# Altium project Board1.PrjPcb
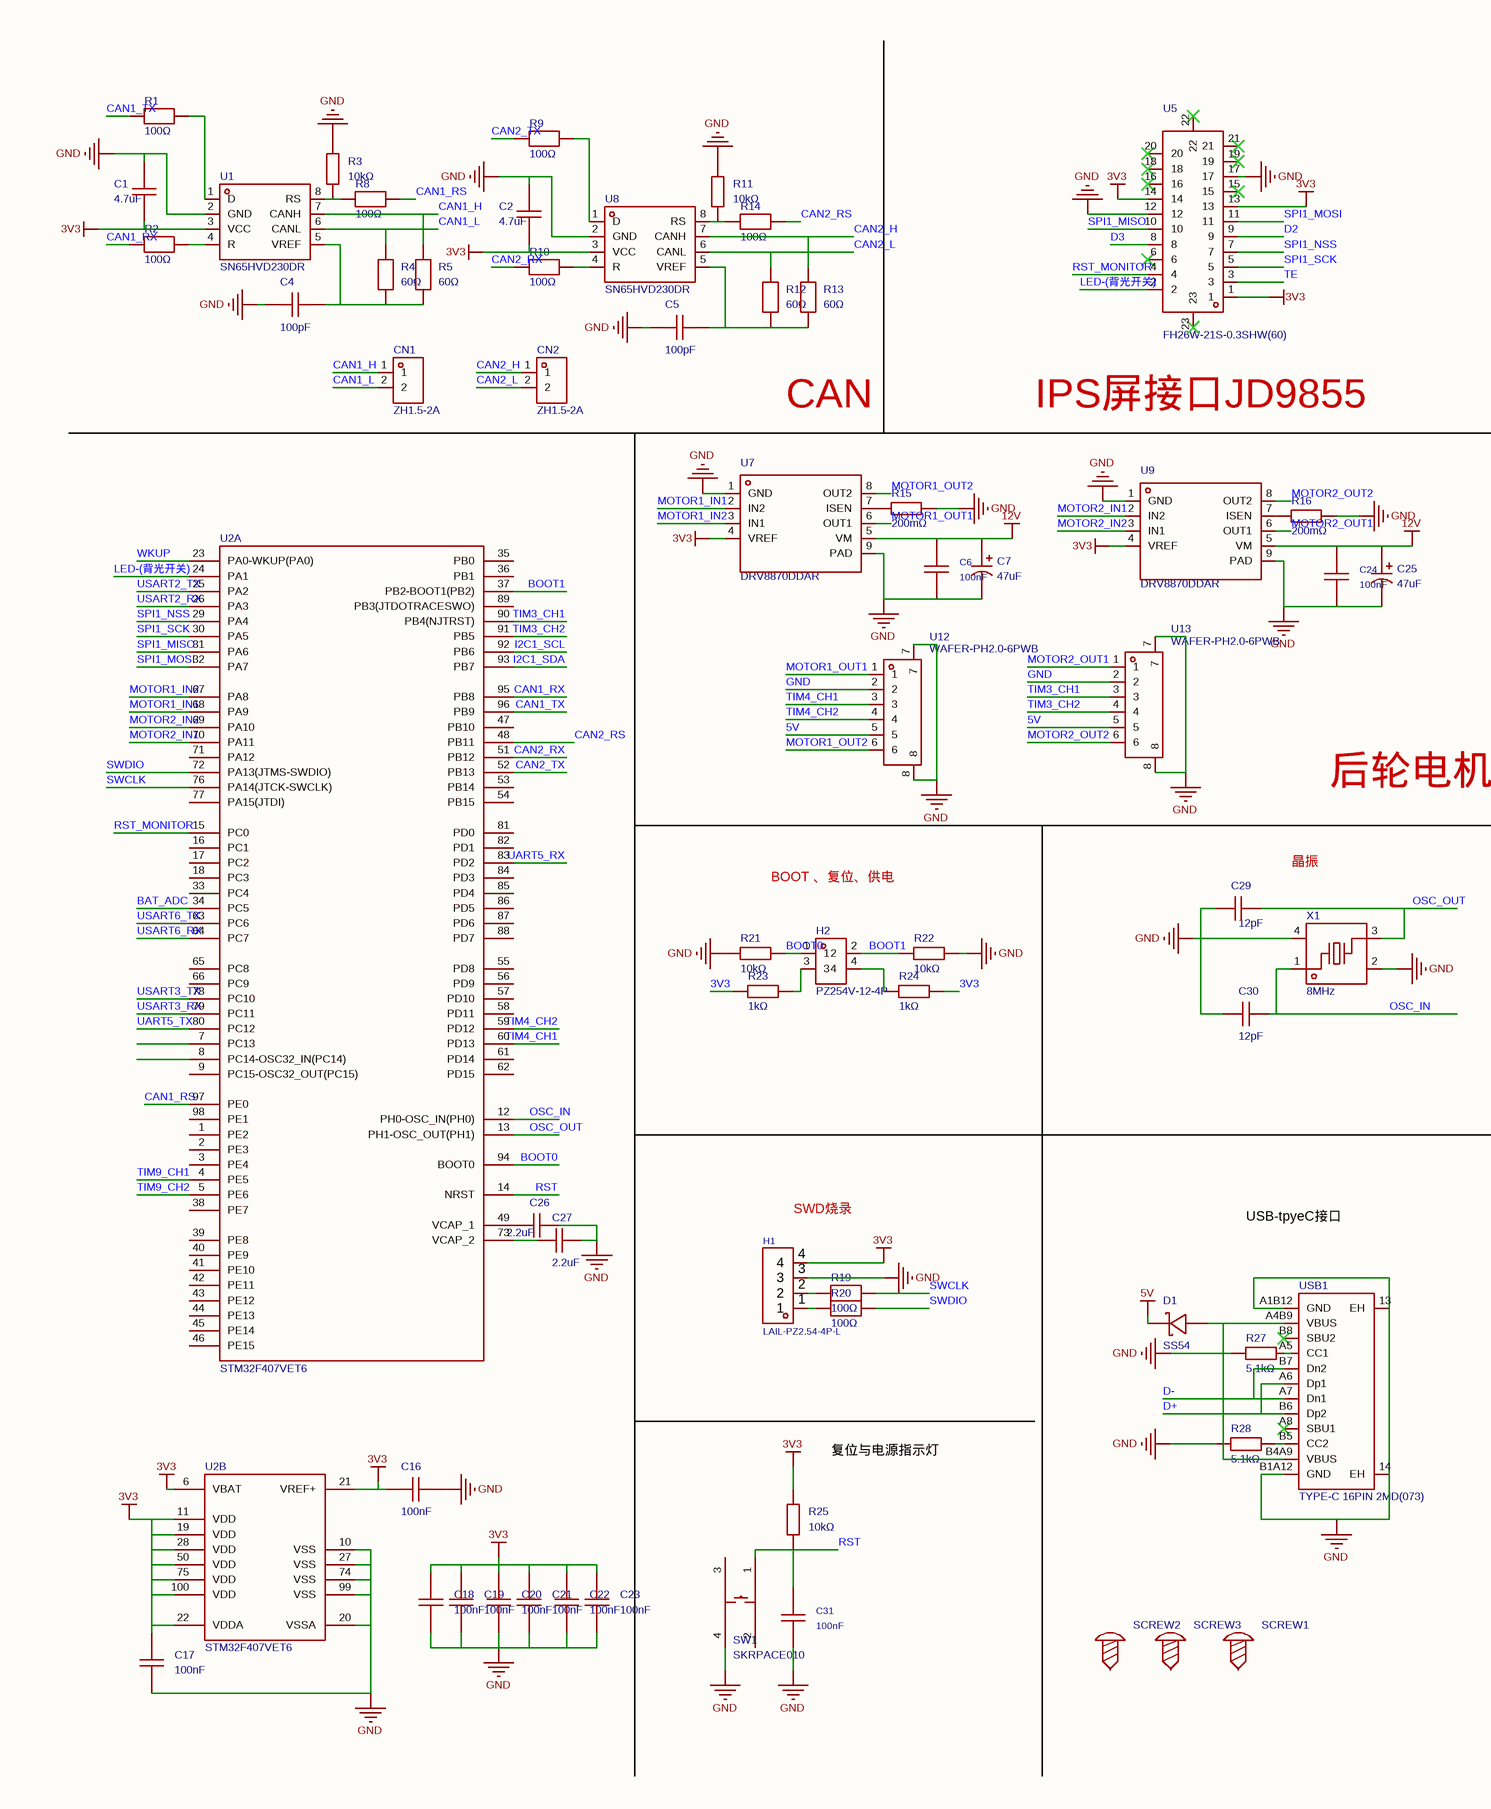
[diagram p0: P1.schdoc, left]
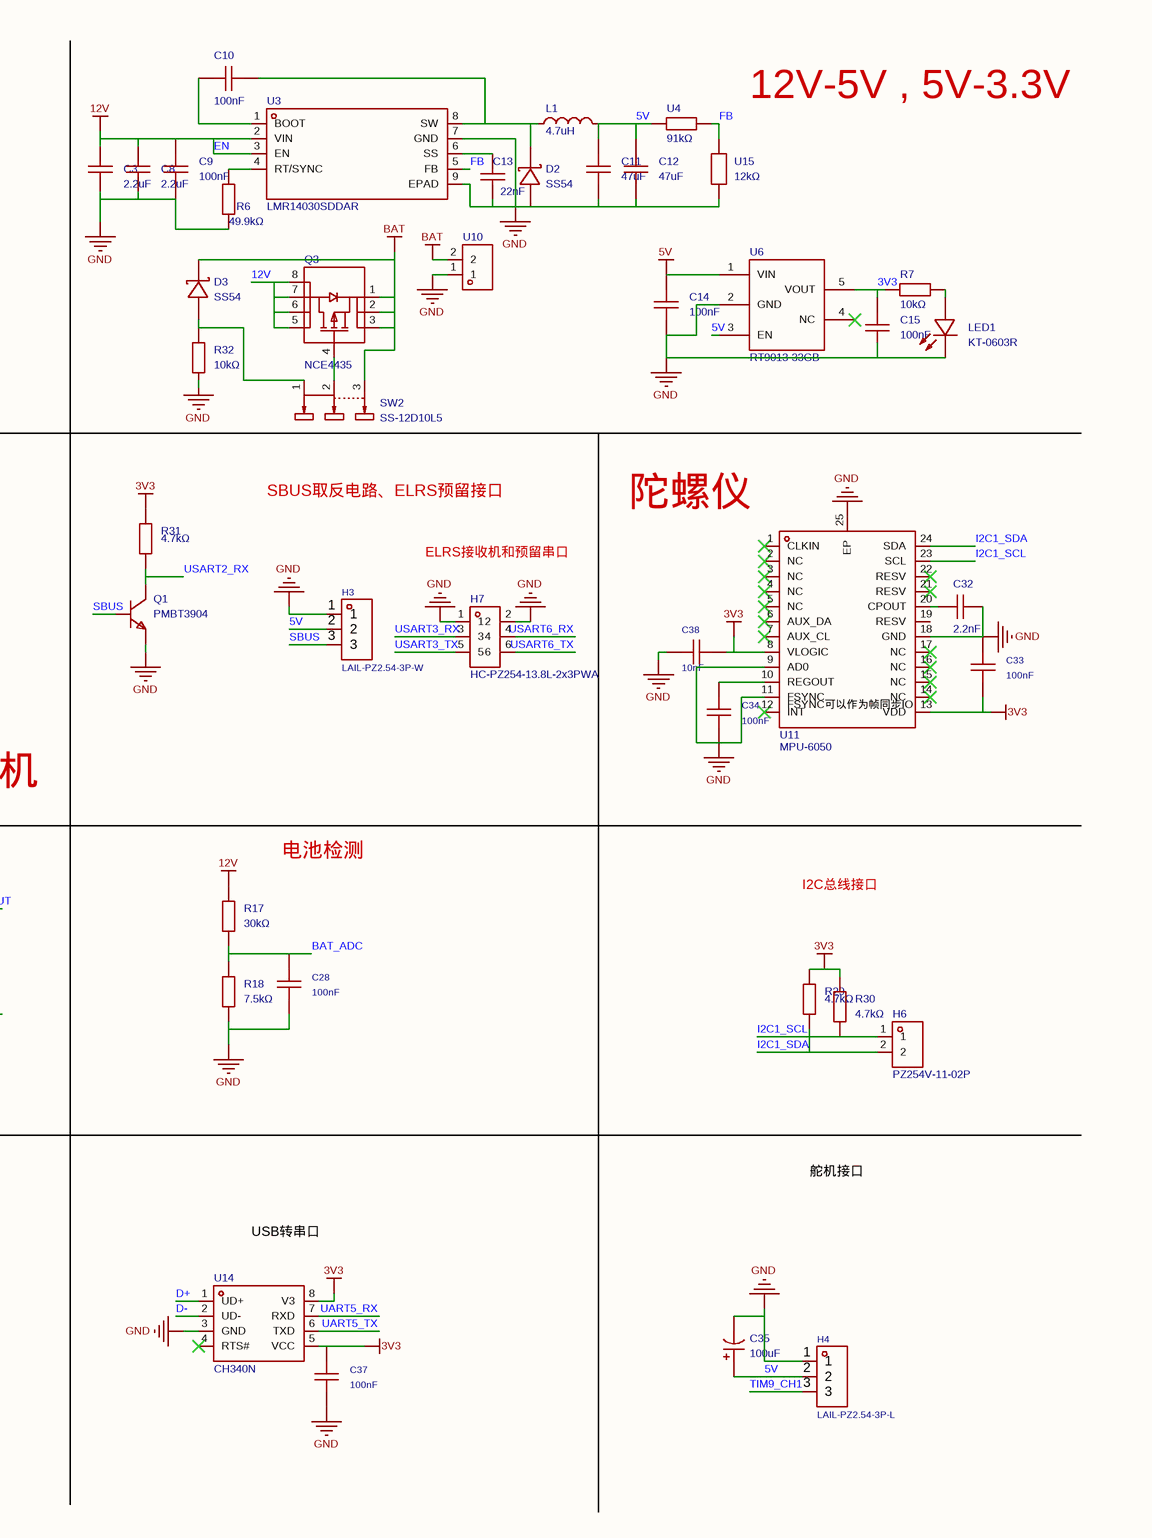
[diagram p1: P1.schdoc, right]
1 sheet, 105 parts. Net scope: global (net labels, ports and power ports of the same name join across sheets).
Board file: PCB1.pcbdoc

## Sheet P1.schdoc
size 420 x 297 mm; Symbol: Drawing-Symbol_A4; Company: 嘉立创EDA; Version: V1.0; Page Size: A4; @Project Name: 车载OBD多参数显示终端; @Update Date: 2026-09-29; @Create Date: 2026-09-29; Device: Drawing-Symbol_A4; @Board Name: Board1; @Page Name: P1; @Create Time: 15:11:10; @Page Count: 1; @Page No: 1; @Schematic Name: Schematic1; @Update Time: 15:11:10; @Assembly Variant: Basic; Border: 1; Title Block Position: 3; Size: A4; Width: 1655; Height: 1170; Region Start: 1; X Region Count: 6; Y Region Count: 4; Blade Width: 10

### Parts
C1  4.7uF  [C0402]
C2  4.7uF  [C0402]
C3  2.2uF  [C0603]
C4  100pF  [C0402]
C5  100pF  [C0402]
C6  100nF  [C0603]
C7  47uF  [CAP-SMD_BD6.3-L6.6-W6.6-LS7.3-FD]
C8  2.2uF  [C0603]
C9  100nF  [C0603]
C10  100nF  [C0603]
C11  47uF  [C1210]
C12  47uF  [C1210]
C13  22nF  [C0603]
C14  100nF  [C0603]
C15  100nF  [C0603]
C16  100nF  [C0603]
C17  100nF  [C0603]
C18  100nF  [C0603]
C19  100nF  [C0603]
C20  100nF  [C0603]
C21  100nF  [C0603]
C22  100nF  [C0603]
C23  100nF  [C0603]
C24  100nF  [C0603]
C25  47uF  [CAP-SMD_BD6.3-L6.6-W6.6-LS7.3-FD]
C26  2.2uF  [C0603]
C27  2.2uF  [C0603]
C28  100nF  [C0603]
C29  12pF  [C0402]
C30  12pF  [C0402]
C31  100nF  [C0603]
C32  2.2nF  [C0603]
C33  100nF  [C0603]
C34  100nF  [C0603]
C35  100uF  [CAP-SMD_BD6.3-L6.6-W6.6-LS7.3-FD-H7.7]
C37  100nF  [C0603]
C38  10nF  [C0603]
CN1  ZH1.5-2A  [CONN-TH_ZH-1.5-2A]
CN2  ZH1.5-2A  [CONN-TH_ZH-1.5-2A]
D1  SS54  [SMA_L4.4-W2.8-LS5.4-R-RD]
D2  SS54  [SMA_L4.4-W2.8-LS5.4-R-RD]
D3  SS54  [SMA_L4.4-W2.8-LS5.4-R-RD]
H1  LAIL-PZ2.54-4P-L  [CONN-TH_LAIL-PZ2.54-4P-L]
H2  PZ254V-12-4P  [HDR-TH_4P-P2.54-V-M-R2-C2-S2.54]
H3  LAIL-PZ2.54-3P-W  [HDR-TH_LAIL-PZ2.54-3P-W]
H4  LAIL-PZ2.54-3P-L  [HDR-TH_3P-P2.54-V-M-1]
H6  PZ254V-11-02P  [HDR-TH_2P-P2.54-V-M]
H7  HC-PZ254-13.8L-2x3PWA  [HDR-TH_6P-P2.54-H-M-R2-C3-S2.54-W12.9]
L1  4.7uH  [IND-SMD_L7.0-W6.6_AAPS0630]
LED1  KT-0603R  [LED-SMD_L1.6-W0.8-R-RD]
Q1  PMBT3904  [SOT-23-3_L2.9-W1.3-P1.90-LS2.4-BR]
Q3  NCE4435  [SOP-8_L5.0-W4.0-P1.27-LS6.2-BL]
R1  100Ω  [R0603]
R2  100Ω  [R0603]
R3  10kΩ  [R0603]
R4  60Ω  [R0603]
R5  60Ω  [R0603]
R6  49.9kΩ  [R0603]
R7  10kΩ  [R0603]
R8  100Ω  [R0603]
R9  100Ω  [R0603]
R10  100Ω  [R0603]
R11  10kΩ  [R0603]
R12  60Ω  [R0603]
R13  60Ω  [R0603]
R14  100Ω  [R0603]
R15  200mΩ  [R1206]
R16  200mΩ  [R1206]
R17  30kΩ  [R0603]
R18  7.5kΩ  [R0603]
R19  100Ω  [R0603]
R20  100Ω  [R0603]
R21  10kΩ  [R0603]
R22  10kΩ  [R0603]
R23  1kΩ  [R0603]
R24  1kΩ  [R0603]
R25  10kΩ  [R0603]
R27  5.1kΩ  [R0603]
R28  5.1kΩ  [R0603]
R29  4.7kΩ  [R0603]
R30  4.7kΩ  [R0603]
R31  4.7kΩ  [R0603]
R32  10kΩ  [R0603]
SCREW1  (no value)  [M3螺丝]
SCREW2  (no value)  [M3螺丝]
SCREW3  (no value)  [M3螺丝]
SW1  SKRPACE010  [KEY-SMD_4P-L4.2-W3.2-P2.20-LS4.6]
SW2  SS-12D10L5  [SW-TH_SS-12D10L5]
U1  SN65HVD230DR  [SOIC-8_L4.9-W3.9-P1.27-LS6.0-BL]
U2  STM32F407VET6  [LQFP-100_L14.0-W14.0-P0.50-LS16.0-BL]  (parts A,B of 2)
U3  LMR14030SDDAR  [SO-8_L4.9-W3.9-P1.27-LS6.0-BL-EP]
U4  91kΩ  [R0603]
U5  FH26W-21S-0.3SHW(60)  [FPC-SMD_21P-P0.30_HDGC_0.3K-QX-21PWB]
U6  RT9013-33GB  [SOT-23-5_L3.0-W1.7-P0.95-LS2.8-BL]
U7  DRV8870DDAR  [HSOP-8_L5.0-W4.0-P1.27-LS6.2-BL-EP]
U8  SN65HVD230DR  [SOIC-8_L4.9-W3.9-P1.27-LS6.0-BL]
U9  DRV8870DDAR  [HSOP-8_L5.0-W4.0-P1.27-LS6.2-BL-EP]
U10  DG305-5.0-02P-12-00A(H)  [CONN-TH_2P-P2.50_DG305-5.0-02P-12-00A-H]  (value not drawn)
U11  MPU-6050  [QFN-24_L4.0-W4.0-P0.50-BL-EP2.7]
U12  WAFER-PH2.0-6PWB  [CONN-SMD_6P-P2.00_XUNPU_WAFER-PH2.0-6PWB]
U13  WAFER-PH2.0-6PWB  [CONN-SMD_6P-P2.00_XUNPU_WAFER-PH2.0-6PWB]
U14  CH340N  [SOP-8_L4.9-W3.9-P1.27-LS6.0-BL]
U15  12kΩ  [R0603]
USB1  TYPE-C 16PIN 2MD(073)  [USB-C-SMD_TYPE-C-16PIN-2MD-073]
X1  8MHz  [CRYSTAL-SMD_4P-L3.2-W2.5-BL]

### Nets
3V3: C1.2 C2.2 C15.2 C16.1 C17.2 C18.2 C19.2 C20.2 C21.2 C22.2 C23.2 C33.1 C37.2 C38.2 H1.4 R7.1 R23.1 R24.2 R25.2 R29.2 R30.2 R31.2 U1.3(VCC) U2.6(VBAT) U2.11(VDD) U2.19(VDD) U2.21(VREF+) U2.22(VDDA) U2.28(VDD) U2.50(VDD) U2.75(VDD) U2.100(VDD) U5.1 U5.13 U5.14 U6.5(VOUT) U7.4(VREF) U8.3(VCC) U9.4(VREF) U11.8(VLOGIC) U11.13(VDD) U14.5(VCC) U14.8(V3)
5V: C11.2 C12.2 C14.2 C35.1 D1.2(K) H3.2 H4.2 L1.2 U4.2 U6.1(VIN) U6.3(EN) U12.5 U13.5
12V: C3.1 C6.2 C7.1 C8.1 C9.2 C24.2 C25.1 Q3.5(D) Q3.6(D) Q3.7(D) Q3.8(D) R17.2 U3.2(VIN) U3.3(EN) U7.5(VM) U9.5(VM)  [also labelled EN]
BAT: D3.2(K) Q3.1(S) Q3.2(S) Q3.3(S) SW2.3 U10.2
GND: C1.1 C2.1 C3.2 C4.2 C5.2 C6.1 C7.2 C8.2 C9.1 C11.1 C12.1 C13.1 C14.1 C15.1 C16.2 C17.1 C18.1 C19.1 C20.1 C21.1 C22.1 C23.1 C24.1 C25.2 C26.2 C27.2 C28.1 C29.1 C30.1 C31.1 C32.2 C33.2 C34.1 C35.2 C37.1 C38.1 D2.1(A) H1.3 H3.1 H4.1 H7.1 H7.2 LED1.2(K) Q1.2(E) R3.2 R6.1 R11.2 R15.2 R16.2 R18.1 R21.1 R22.2 R27.1 R28.1 R32.2 SW1.4 U1.2(GND) U2.10(VSS) U2.20(VSSA) U2.27(VSS) U2.74(VSS) U2.99(VSS) U3.7(GND) U3.9(EPAD) U5.12 U5.17 U6.2(GND) U7.1(GND) U7.9(PAD) U8.2(GND) U9.1(GND) U9.9(PAD) U10.1 U11.9(AD0) U11.11(FSYNC) U11.18(GND) U11.25(EP) U12.2 U12.7 U12.8 U13.2 U13.7 U13.8 U14.3(GND) U15.1 USB1.13(EH) USB1.14(EH) USB1.A1B12(GND) USB1.B1A12(GND) X1.2(GND) X1.4(GND)
BAT_ADC: C28.2 R17.1 R18.2 U2.34(PC5)
BOOT0: H2.1 R21.2 U2.94(BOOT0)
BOOT1: H2.2 R22.1 U2.37(PB2-BOOT1(PB2))
CAN1_H: CN1.1 R5.2 U1.7(CANH)
CAN1_L: CN1.2 R4.2 U1.6(CANL)
CAN1_RS: R8.2 U2.97(PE0)
CAN1_RX: R2.1 U2.95(PB8)
CAN1_TX: R1.1 U2.96(PB9)
CAN2_H: CN2.1 R13.2 U8.7(CANH)
CAN2_L: CN2.2 R12.2 U8.6(CANL)
CAN2_RS: R14.2 U2.48(PB11)
CAN2_RX: R10.1 U2.51(PB12)
CAN2_TX: R9.1 U2.52(PB13)
D2: U5.9
D3: U5.8
D+: U14.1(UD+) USB1.A6(Dp1) USB1.B6(Dp2)
D-: U14.2(UD-) USB1.A7(Dn1) USB1.B7(Dn2)
FB: U3.5(FB) U4.1 U15.2
I2C1_SCL: H6.1 R30.1 U2.92(PB6) U11.23(SCL)
I2C1_SDA: H6.2 R29.1 U2.93(PB7) U11.24(SDA)
LED-(背光开关): U2.24(PA1) U5.2
MOTOR1_IN1: U2.68(PA9) U7.2(IN2)
MOTOR1_IN2: U2.67(PA8) U7.3(IN1)
MOTOR1_OUT1: U7.6(OUT1) U12.1
MOTOR1_OUT2: U7.8(OUT2) U12.6
MOTOR2_IN1: U2.70(PA11) U9.2(IN2)
MOTOR2_IN2: U2.69(PA10) U9.3(IN1)
MOTOR2_OUT1: U9.6(OUT1) U13.1
MOTOR2_OUT2: U9.8(OUT2) U13.6
OSC_IN: C30.2 U2.12(PH0-OSC_IN(PH0)) X1.1
OSC_OUT: C29.2 U2.13(PH1-OSC_OUT(PH1)) X1.3
RST: C31.2 R25.1 SW1.1 U2.14(NRST)
RST_MONITOR: U2.15(PC0) U5.4
SBUS: H3.3 Q1.1(B)
SPI1_MISO: U2.31(PA6) U5.10
SPI1_MOSI: U2.32(PA7) U5.11
SPI1_NSS: U2.29(PA4) U5.7
SPI1_SCK: U2.30(PA5) U5.5
SWCLK: R19.2 U2.76(PA14(JTCK-SWCLK))
SWDIO: R20.2 U2.72(PA13(JTMS-SWDIO))
TE: U5.3
TIM3_CH1: U2.90(PB4(NJTRST)) U13.3
TIM3_CH2: U2.91(PB5) U13.4
TIM4_CH1: U2.60(PD13) U12.3
TIM4_CH2: U2.59(PD12) U12.4
TIM9_CH1: H4.3 U2.4(PE5)
TIM9_CH2: U2.5(PE6)
UART5_RX: U2.83(PD2) U14.7(RXD)
UART5_TX: U2.80(PC12) U14.6(TXD)
USART2_RX: Q1.3(C) R31.1 U2.26(PA3)
USART2_TX: U2.25(PA2)
USART3_RX: H7.3 U2.79(PC11)
USART3_TX: H7.5 U2.78(PC10)
USART6_RX: H7.4 U2.64(PC7)
USART6_TX: H7.6 U2.63(PC6)
WKUP: U2.23(PA0-WKUP(PA0))
NetC4_1: C4.1 R4.1 R5.1 U1.5(VREF)
NetC5_1: C5.1 R12.1 R13.1 U8.5(VREF)
NetC10_1: C10.1 D2.2(K) L1.1 U3.8(SW)
NetC10_2: C10.2 U3.1(BOOT)
NetC13_2: C13.2 U3.6(SS)
NetC26_1: C26.1 U2.49(VCAP_1)
NetC27_1: C27.1 U2.73(VCAP_2)
NetC32_1: C32.1 U11.20(CPOUT)
NetC34_2: C34.2 U11.10(REGOUT)
NetD1_1: D1.1(A) USB1.A4B9(VBUS) USB1.B4A9(VBUS)
NetD3_1: D3.1(A) R32.1 SW2.1
NetH1_1: H1.1 R20.1
NetH1_2: H1.2 R19.1
NetH2_3: H2.3 R23.2
NetH2_4: H2.4 R24.1
NetLED1_1: LED1.1(A) R7.2
NetQ3_4: Q3.4(G) SW2.2
NetR1_2: R1.2 U1.1(D)
NetR2_2: R2.2 U1.4(R)
NetR3_1: R3.1 R8.1 U1.8(RS)
NetR6_2: R6.2 U3.4(RT/SYNC)
NetR9_2: R9.2 U8.1(D)
NetR10_2: R10.2 U8.4(R)
NetR11_1: R11.1 R14.1 U8.8(RS)
NetR15_1: R15.1 U7.7(ISEN)
NetR16_1: R16.1 U9.7(ISEN)
NetR27_2: R27.2 USB1.A5(CC1)
NetR28_2: R28.2 USB1.B5(CC2)

Not connected (* = marked no-connect by the designer): SCREW1 1; SCREW2 1; SCREW3 1; SW1 2 3; U2 1(PE2) 2(PE3) 3(PE4) 7(PC13) 8(PC14-OSC32_IN(PC14)) 9(PC15-OSC32_OUT(PC15)) 16(PC1) 17(PC2) 18(PC3) 33(PC4) 35(PB0) 36(PB1) 38(PE7) 39(PE8) 40(PE9) 41(PE10) 42(PE11) 43(PE12) 44(PE13) 45(PE14) 46(PE15) 47(PB10) 53(PB14) 54(PB15) 55(PD8) 56(PD9) 57(PD10) 58(PD11) 61(PD14) 62(PD15) 65(PC8) 66(PC9) 71(PA12) 77(PA15(JTDI)) 81(PD0) 82(PD1) 84(PD3) 85(PD4) 86(PD5) 87(PD6) 88(PD7) 89(PB3(JTDOTRACESWO)) 98(PE1); U5 6* 15* 16* 18* 19* 20* 21* 22* 23*; U6 4(NC)*; U11 1(CLKIN)* 2(NC)* 3(NC)* 4(NC)* 5(NC)* 6(AUX_DA)* 7(AUX_CL)* 12(INT)* 14(NC)* 15(NC)* 16(NC)* 17(NC)* 19(RESV) 21(RESV)* 22(RESV)*; U14 4(RTS#)*; USB1 A8(SBU1)* B8(SBU2)*

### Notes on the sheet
- 12V-5V , 5V-3.3V
- CAN
- IPS屏接口JD9855
- SBUS取反电路、ELRS预留接口
- 陀螺仪
- ELRS接收机和预留串口
- (near U11) FSYNC可以作为帧同步IO
- 后轮电机
- BOOT 、复位、供电
- 晶振
- 电池检测
- I2C总线接口
- (near H1) SWD烧录
- USB-tpyeC接口
- 舵机接口
- USB转串口
- (near R25) 复位与电源指示灯

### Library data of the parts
C1 = CGA0402X5R475M250GT: 容值:4.7uF;精度:±20%;额定电压:25V;温度系数:X5R;; Manufacturer: HRE(芯声); Check: true; AddInBom: yes; ModelId: 36a51122f27c49738f86b3bfa98863e00819f05c4eef4c71ace90d822a990e87; ModelName: C0402_L1.0-W0.5-H0.5; ModelTransform: 39.37,19.685,0,0,0,0,0,0,0; Tolerance: ±20%; Voltage Rating: 25V; Temperature Coefficient: X5R
C2 = CGA0402X5R475M250GT: 容值:4.7uF;精度:±20%;额定电压:25V;温度系数:X5R;; Manufacturer: HRE(芯声); 3D Model: 36a51122f27c49738f86b3bfa98863e00819f05c4eef4c71ace90d822a990e87; 3D Model Transform: 39.37,19.685,0,0,0,0,0,0,0; Tolerance: ±20%; Voltage Rating: 25V; Temperature Coefficient: X5R; Check: true; AddInBom: yes; ModelName: C0402_L1.0-W0.5-H0.5
C3 C8 = CL10A225KO8NNNC: 容值:2.2uF;精度:±10%;额定电压:16V;温度系数:X5R;; Manufacturer: SAMSUNG(三星); Add into BOM: yes; 3D Model: ac125912035d415993ca9572d50418b1; 3D Model Transform: 62.992,31.496,0,0,0,0,0,0,0; Tolerance: ±10%; Voltage Rating: 16V; Temperature Coefficient: X5R; ModelName: C0603_L1.6-W0.8-H0.8
C4 = CSA0402C0G101J500GT: 容值:100pF;精度:±5%;额定电压:50V;温度系数:C0G;; Manufacturer: HRE(芯声); AddInBom: yes; ModelId: 36a51122f27c49738f86b3bfa98863e00819f05c4eef4c71ace90d822a990e87; ModelName: C0402_L1.0-W0.5-H0.5; ModelTransform: 39.37,19.685,0,0,0,0,0,0,0; Tolerance: ±5%; Voltage Rating: 50V; Temperature Coefficient: C0G
C5 = CSA0402C0G101J500GT: 容值:100pF;精度:±5%;额定电压:50V;温度系数:C0G;; Manufacturer: HRE(芯声); 3D Model: 36a51122f27c49738f86b3bfa98863e00819f05c4eef4c71ace90d822a990e87; 3D Model Transform: 39.37,19.685,0,0,0,0,0,0,0; Tolerance: ±5%; Voltage Rating: 50V; Temperature Coefficient: C0G; AddInBom: yes; ModelName: C0402_L1.0-W0.5-H0.5
C6 C9 C10 C14-C24 C28 C31 C33 C34 C37 = FCC0603B104K500CT: 容值:100nF;精度:±10%;额定电压:50V;温度系数:X7R;; Manufacturer: FOJAN(富捷); 3D Model: ac125912035d415993ca9572d50418b1; 3D Model Transform: 62.992,31.496,0,0,0,0,0,0,0; Tolerance: ±10%; Voltage Rating: 50V; Temperature Coefficient: X7R; AddInBom: yes; ModelName: C0603_L1.6-W0.8-H0.8
C7 C25 = RV50V47M6X5: 容值:47uF;精度:±20%;额定电压:50V;纹波电流:50mA@120Hz;; Manufacturer: JIERR(捷而瑞); AddInBom: yes; ModelId: 697a8c63e3274188b68c96045bc3ea1c0819f05c4eef4c71ace90d822a990e87; ModelTransform: 287.401,259.842,0,180,0,0,0.001,0.001,0; Tolerance: ±20%; Voltage Rating: 50V; Lifetime: 2000hrs@105℃
C11 C12 = CS3225X7R476K160NRL: 容值:47uF;精度:±10%;额定电压:16V;温度系数:X7R;; Manufacturer: SAMWHA(三和); AddInBom: yes; ModelId: 833068e7fe044595a6eec77c561794550819f05c4eef4c71ace90d822a990e87; ModelName: C1210_L3.2-W2.5-H2.5; ModelTransform: 125.984,98.425,0,0,0,0,0,0,0; Tolerance: ±10%; Voltage Rating: 16V; Temperature Coefficient: X7R
C13 = CL10B223KB8NNNC: 容值:22nF;精度:±10%;额定电压:50V;温度系数:X7R;; Manufacturer: SAMSUNG(三星); AddInBom: yes; ModelId: ac125912035d415993ca9572d50418b10819f05c4eef4c71ace90d822a990e87; ModelName: C0603_L1.6-W0.8-H0.8; ModelTransform: 62.992,31.496,0,0,0,0,0,0,0; Tolerance: ±10%; Voltage Rating: 50V; Temperature Coefficient: X7R
C26 C27 = CL10A225KO8NNNC: 容值:2.2uF;精度:±10%;额定电压:16V;温度系数:X5R;; Manufacturer: SAMSUNG(三星); AddInBom: yes; ModelId: ac125912035d415993ca9572d50418b10819f05c4eef4c71ace90d822a990e87; ModelName: C0603_L1.6-W0.8-H0.8; ModelTransform: 62.992,31.496,0,0,0,0,0,0,0; Tolerance: ±10%; Voltage Rating: 16V; Temperature Coefficient: X5R
C29 C30 = 0402CG120J500NT: 容值:12pF;精度:±5%;额定电压:50V;温度系数:C0G;; Manufacturer: FH(风华); AddInBom: yes; ModelId: 36a51122f27c49738f86b3bfa98863e00819f05c4eef4c71ace90d822a990e87; ModelName: C0402_L1.0-W0.5-H0.5; ModelTransform: 39.37,19.685,0,0,0,0,0,0,0; Tolerance: ±5%; Voltage Rating: 50V; Temperature Coefficient: C0G
C32 = 0603B222K500NT: 容值:2.2nF;精度:±10%;额定电压:50V;温度系数:X7R;; Manufacturer: FH(风华); AddInBom: yes; ModelId: ac125912035d415993ca9572d50418b10819f05c4eef4c71ace90d822a990e87; ModelName: C0603_L1.6-W0.8-H0.8; ModelTransform: 62.992,31.496,0,0,0,0,0,0,0; Tolerance: ±10%; Voltage Rating: 50V; Temperature Coefficient: X7R
C35 = JVJ50V100M6x8: 容值:100uF;精度:±20%;额定电压:50V;纹波电流:140mA@120Hz;; Manufacturer: JIERR(捷而瑞); AddInBom: yes; ModelId: ccbda52dceed4b139172c40f75c9da3f0819f05c4eef4c71ace90d822a990e87; ModelTransform: 287.401,259.842,0,0,0,0,0,0,0; Tolerance: ±20%; Voltage Rating: 50V; Lifetime: 2000hrs@105℃
C38 = 0603B103K500NT: 容值:10nF;精度:±10%;额定电压:50V;温度系数:X7R;; Manufacturer: FH(风华); AddInBom: yes; ModelId: ac125912035d415993ca9572d50418b10819f05c4eef4c71ace90d822a990e87; ModelName: C0603_L1.6-W0.8-H0.8; ModelTransform: 62.992,31.496,0,0,0,0,0,0,0; Tolerance: ±10%; Voltage Rating: 50V; Temperature Coefficient: X7R
CN1 CN2 = ZH1.5-2A: 插针结构:1x2P;间距:1.5mm;安装方式:直插;参考系列:ZH;总PIN数:2P;排数:1;每排PIN数:2;行距:-;额定电流:1A;触头材质:黄铜;触头镀层:锡;工作温度:-25℃~+85℃;; Manufacturer: CAX(创都); Symbol: ZH1.5-2A_C722910; AddInBom: yes; ModelId: d349299c92334193818eceb57c024ca40819f05c4eef4c71ace90d822a990e87; ModelTransform: 177.165,149.606,0,0,0,0,0,15.512,-118.11; Pins Structure: 1x2P; Pitch: 1.5mm; Reference Series: ZH; Number of PINs Per Row: 2; Current Rating: 1A; Voltage Rating: 100V; Plastic Material: PA66; Flame Retardant Rating: UL94V-0; Z-Height of the Board: 4.6mm; Y-Width of Bottom Edge on Board: 3.75mm
D1 D3 = SS54_C22452: 二极管配置:独立式;正向压降(Vf):550mV@5A;直流反向耐压(Vr):40V;整流电流:5A;; Manufacturer: MDD(辰达半导体); 3D Model: 228de99b63224bd3982b21290755dd840819f05c4eef4c71ace90d822a990e87; 3D Model Transform: 204.724,110.236,0,0,0,0,0,0,0; Diode Configuration: 独立式; Voltage - DC Reverse(Vr): 40V; Current - Rectified: 5A; Reverse Leakage Current (Ir): 1mA@40V; Operating Junction Temperature Range: -55℃~+125℃; AddInBom: yes
D2 = SS54_C22452: 二极管配置:独立式;正向压降(Vf):550mV@5A;直流反向耐压(Vr):40V;整流电流:5A;; Manufacturer: MDD(辰达半导体); AddInBom: yes; ModelId: 228de99b63224bd3982b21290755dd840819f05c4eef4c71ace90d822a990e87; ModelTransform: 204.724,110.236,0,0,0,0,0,0,0; Diode Configuration: 独立式; Voltage - DC Reverse(Vr): 40V; Current - Rectified: 5A; Reverse Leakage Current (Ir): 1mA@40V; Operating Junction Temperature Range: -55℃~+125℃
H1 = LAIL-PZ2.54-4P-L: 插针结构:1x4P;间距:2.54mm;圆针/方针:方针;排数:单排;总PIN位数:4P;额定电流:3A;额定电压:250V;塑高:2.5mm;端接针长度:3mm;触头材质:黄铜;触头镀层:金;工作温度:-25℃~+80℃;颜色:黑色;; Manufacturer: 莱联; AddInBom: yes; ModelId: 112b012cb4004446aa5386c9c86d05f00819f05c4eef4c71ace90d822a990e87; ModelTransform: 400.039,100,0,0,0,0,0,0,-118.11; Pin Structure: 1x4P; Pitch: 2.54mm; Circluar Pins/Square Pins: 方针; Current Rating: 3A; Voltage Rating (Max): 250V
H2 = PZ254V-12-4P: 插针结构:2x2P;间距:2.54mm;行距:2.54mm;圆针/方针:方针;安装方式:直插;排数:双排;总PIN位数:4P;额定电流:-;额定电压:-;配合针长度:6mm;塑高:2.5mm;端接针长度:3mm;触头材质:黄铜;触头镀层:-;工作温度:-40℃~+105℃;颜色:黑色;; Manufacturer: XFCN(兴飞); AddInBom: yes; ModelId: 396726ecc332483f84428c142640bc150819f05c4eef4c71ace90d822a990e87; ModelName: HDR-TH_4P-P2.54-M-LI-2X2P; ModelTransform: 200.03897,196.85,0,0,0,0,0,0,-118.11; Pin Structure: 2x2P; Pitch: 2.54mm; Circluar Pins/Square Pins: 方针
H3 = LAIL-PZ2.54-3P-W: 插针结构:1x3P;间距:2.54mm;圆针/方针:方针;安装方式:弯插;排数:单排;总PIN位数:3P;额定电流:3A;额定电压:250V;配合针长度:6mm;塑高:2.5mm;触头材质:黄铜;触头镀层:金;工作温度:-25℃~+80℃;颜色:黑色;; Manufacturer: LAILAN(莱联); AddInBom: yes; ModelId: c29f0863625345319e19055e1dc6212d0819f05c4eef4c71ace90d822a990e87; ModelTransform: 300.3931,407.0858,0,0,0,0,0,-190.157,-118.11; Pin Structure: 1x3P; Pitch: 2.54mm; Circluar Pins/Square Pins: 方针; Current Rating: 3A; Voltage Rating (Max): 250V
H4 = LAIL-PZ2.54-3P-L: 插针结构:1x3P;间距:2.54mm;圆针/方针:方针;安装方式:直插;排数:单排;总PIN位数:3P;额定电流:3A;额定电压:250V;配合针长度:6mm;塑高:2.5mm;端接针长度:3mm;触头材质:黄铜;触头镀层:金;工作温度:-25℃~+80℃;颜色:黑色;; Manufacturer: LAILAN(莱联); AddInBom: yes; ModelId: 94a8ffe137b6410295cb18cd3ffd99db0819f05c4eef4c71ace90d822a990e87; ModelName: HDR-M-2.54_1x3; ModelTransform: 299.9994,100,0,0,0,0,0,0,-118.11; Pin Structure: 1x3P; Pitch: 2.54mm; Circluar Pins/Square Pins: 方针; Current Rating: 3A; Voltage Rating (Max): 250V
H6 = PZ254V-11-02P: 插针结构:1x2P;间距:2.54mm;行距:-;圆针/方针:方针;安装方式:直插;排数:单排;总PIN位数:2P;额定电流:3A;额定电压:250V;配合针长度:6.1mm;塑高:2.5mm;端接针长度:3mm;触头材质:黄铜;触头镀层:金;工作温度:-40℃~+105℃;颜色:黑色;; Manufacturer: XFCN(兴飞); AddInBom: yes; ModelId: e35305ec3aa84b66b849f914b715e73f0819f05c4eef4c71ace90d822a990e87; ModelName: HDR2.54-M-LI-1X2P; ModelTransform: 200,100,0,0,0,0,0,0,-118.11; Pin Structure: 1x2P; Pitch: 2.54mm; Circluar Pins/Square Pins: 方针; Current Rating: 3A; Voltage Rating (Max): 250V
H7 = HC-PZ254-13.8L-2x3PWA: 插针结构:2x3P;间距:2.54mm;行距:2.54mm;圆针/方针:方针;安装方式:弯插;排数:双排;总PIN位数:6P;额定电流:3A;额定电压:-;配合针长度:6mm;塑高:5.04mm;端接针长度:3mm;触头材质:黄铜;触头镀层:金;工作温度:-40℃~+105℃;颜色:黑色;; Manufacturer: HC(虹成电子); AddInBom: yes; ModelId: 8c97c9e9645742108965c307a3ef82850819f05c4eef4c71ace90d822a990e87; ModelTransform: 300.3931,507.873,0,0,0,0,0.003,-190.949,-118.11; Pin Structure: 2x3P; Pitch: 2.54mm; Circluar Pins/Square Pins: 方针; Current Rating: 3A
L1 = AAPS0630M4R7A: 电感值:4.7uH;精度:±20%;额定电流:6.06A;饱和电流(Isat):9A;; Manufacturer: Coilank(驰兴电感); AddInBom: yes; ModelId: 359e35ddf75a4a709731526095ca39680819f05c4eef4c71ace90d822a990e87; ModelTransform: 303.149,260.2357,0,0,0,0,0,0,0; Tolerance: ±20%; Current Rating: 6.06A; Current - Saturation(Isat): 9A; DC Resistance(DCR): 32.5mΩ
LED1 = KT-0603R: 灯头类型:1.6mmx0.8mm方形灯头;发光颜色:红色;正向压降(Vf):1.8V~2.4V;功率:40mW;正向电流:20mA;波长:615nm~630nm;二极管配置:独立二极管;透镜颜色:无色透明透镜;色温:-;发光强度:300mcd;发光角度:120°;载带方式:-;工作温度:-40℃~+85℃;; Manufacturer: KENTO; AddInBom: yes; ModelId: 866a33bb88064d05820867a448e6f5fc0819f05c4eef4c71ace90d822a990e87; ModelName: LED0603_L1.6-W0.8-H0.6; ModelTransform: 63.7794,31.496,0,0,0,0,-4.528,0,0; Illumination Color: 红色; Power(Watts): 40mW; Forward Current: 20mA; Peak Wavelength: 645nm; Diode Configuration: 独立二极管; Lens Color: 无色透明透镜; Luminous Intensity: 300mcd; Viewing Angle: 120°
Q1 = PMBT3904: 晶体管类型:NPN;集电极电流(Ic):200mA;集射极击穿电压(Vceo):60V;耗散功率(Pd):200mW;直流电流增益(hFE):300;; Manufacturer: PAKER(派克微); AddInBom: yes; ModelId: c62791f0466c4ae2a892c056b845b0ca0819f05c4eef4c71ace90d822a990e87; ModelName: SOT-23-3P_L2.9-W1.3-H1.0-LS2.4-P0.95; ModelTransform: 98.425,114.173,0,180,0,0,0.0005,-0.0005,0; type: NPN; Current - Collector(Ic): 200mA; Collector - Emitter Voltage VCEO: 60V; Pd - Power Dissipation: 200mW; DC Current Gain: 300; Transition frequency(fT): 300MHz; Current - Collector Cutoff: 100nA; Vce Saturation(VCE(sat)): 300mV; Emitter-Base Voltage(Vebo): 6V; Number: 1个NPN; Configuration: 独立式
Q3 = NCE4435: 数量:1个P沟道;漏源电压(Vdss):30V;连续漏极电流(Id):9.1A;导通电阻(RDS(on)):35mΩ@4.5V;耗散功率(Pd):3.1W;阈值电压(Vgs(th)):1.5V;; Manufacturer: NCE(无锡新洁能); AddInBom: yes; ModelId: a3315c1c78f949e6bb82c6eaca1c53c70819f05c4eef4c71ace90d822a990e87; ModelName: SOP-8_L5.0-W4.0-H1.8-LS6.2-P1.27; ModelTransform: 244.094,196.85,0,90,0,0,0,0,0; Number: 1个P沟道; Drain to Source Voltage: 30V; Current - Continuous Drain(Id): 9.1A; Pd - Power Dissipation: 3.1W; Gate Threshold Voltage (Vgs(th)): 1.5V; Gate Charge(Qg): 30nC; Input Capacitance(Ciss): 1.6nF; Reverse Transfer Capacitance (Crss@Vds): 300pF; Type: P沟道; Output Capacitance(Coss): 350pF; Vgs: ±20V
R1 R2 R8-R10 R14 = FRC0603F1000TS: 电阻类型:厚膜电阻;阻值:100Ω;精度:±1%;功率:100mW;工作电压:75V;温度系数:±100ppm/℃;; Manufacturer: FOJAN(富捷); 3D Model: fc143cca1e79419f9cd78b61e9279f08; 3D Model Transform: 31.8897,63.7794,0,90,0,0,0,0,0; Tolerance: ±1%; Power(Watts): 100mW; Voltage-Supply(Max): 75V; AddInBom: yes
R3 R7 R11 = 0603WAF1002T5E: 电阻类型:厚膜电阻;阻值:10kΩ;精度:±1%;功率:100mW;最大工作电压:75V;温度系数:±100ppm/℃;; Manufacturer: UNI-ROYAL(厚声); AddInBom: yes; ModelId: fc143cca1e79419f9cd78b61e9279f08; ModelTransform: 31.8897,63.7794,0,90,0,0,0,0,0; Tolerance: ±1%; Power(Watts): 100mW; Overload Voltage (Max): 75V
R4 R5 = RTT0360R0FTP: 电阻类型:厚膜电阻;阻值:60Ω;精度:±1%;功率:100mW;最大工作电压:75V;温度系数:±100ppm/℃;; Manufacturer: RALEC(旺诠); AddInBom: yes; ModelId: fc143cca1e79419f9cd78b61e9279f080819f05c4eef4c71ace90d822a990e87; ModelTransform: 31.8897,63.7794,0,90,0,0,0,0,0; Tolerance: ±1%; Power(Watts): 100mW; Overload Voltage (Max): 75V
R6 = 0603WAF4992T5E: 电阻类型:厚膜电阻;阻值:49.9kΩ;精度:±1%;功率:100mW;工作电压:75V;温度系数:±100ppm/℃;; Manufacturer: UNI-ROYAL(厚声); AddInBom: yes; ModelId: fc143cca1e79419f9cd78b61e9279f080819f05c4eef4c71ace90d822a990e87; ModelTransform: 31.8897,63.7794,0,90,0,0,0,0,0; Tolerance: ±1%; Power(Watts): 100mW; Voltage-Supply(Max): 75V
R12 R13 = RTT0360R0FTP: 电阻类型:厚膜电阻;阻值:60Ω;精度:±1%;功率:100mW;最大工作电压:75V;温度系数:±100ppm/℃;; Manufacturer: RALEC(旺诠); 3D Model: fc143cca1e79419f9cd78b61e9279f080819f05c4eef4c71ace90d822a990e87; 3D Model Transform: 31.8897,63.7794,0,90,0,0,0,0,0; Tolerance: ±1%; Power(Watts): 100mW; Overload Voltage (Max): 75V; AddInBom: yes
R15 R16 = 1206W4F200LT5E: 电阻类型:厚膜电阻;阻值:200mΩ;精度:±1%;功率:250mW;最大工作电压:200V;温度系数:±800ppm/℃;; Manufacturer: UNI-ROYAL(厚声); AddInBom: yes; ModelId: 89a1f13db2384da588040e0b3c55bf660819f05c4eef4c71ace90d822a990e87; ModelName: R1206_L3.2-W1.6-H0.6; ModelTransform: 125.984,62.992,0,0,0,0,0,0,0; Tolerance: ±1%; Power(Watts): 250mW; Overload Voltage (Max): 200V
R17 = 0603WAF3002T5E: 电阻类型:厚膜电阻;阻值:30kΩ;精度:±1%;功率:100mW;工作电压:75V;温度系数:±100ppm/℃;; Manufacturer: UNI-ROYAL(厚声); AddInBom: yes; ModelId: fc143cca1e79419f9cd78b61e9279f080819f05c4eef4c71ace90d822a990e87; ModelTransform: 31.8897,63.7794,0,90,0,0,0,0,0; Tolerance: ±1%; Power(Watts): 100mW; Voltage-Supply(Max): 75V
R18 = 0603WAF7501T5E: 电阻类型:厚膜电阻;阻值:7.5kΩ;精度:±1%;功率:100mW;工作电压:75V;温度系数:±100ppm/℃;; Manufacturer: UNI-ROYAL(厚声); AddInBom: yes; ModelId: fc143cca1e79419f9cd78b61e9279f080819f05c4eef4c71ace90d822a990e87; ModelTransform: 31.8897,63.7794,0,90,0,0,0,0,0; Tolerance: ±1%; Power(Watts): 100mW; Voltage-Supply(Max): 75V
R19 R20 = FRC0603F1000TS: 电阻类型:厚膜电阻;阻值:100Ω;精度:±1%;功率:100mW;工作电压:75V;温度系数:±100ppm/℃;; Manufacturer: FOJAN(富捷); AddInBom: yes; ModelId: fc143cca1e79419f9cd78b61e9279f080819f05c4eef4c71ace90d822a990e87; ModelTransform: 31.8897,63.7794,0,90,0,0,0,0,0; Tolerance: ±1%; Power(Watts): 100mW; Voltage-Supply(Max): 75V
R21 R22 R25 R32 = 0603WAF1002T5E: 电阻类型:厚膜电阻;阻值:10kΩ;精度:±1%;功率:100mW;最大工作电压:75V;温度系数:±100ppm/℃;; Manufacturer: UNI-ROYAL(厚声); 3D Model: fc143cca1e79419f9cd78b61e9279f08; 3D Model Transform: 31.8897,63.7794,0,90,0,0,0,0,0; Tolerance: ±1%; Power(Watts): 100mW; Overload Voltage (Max): 75V; AddInBom: yes
R23 R24 = 0603WAF1001T5E: 电阻类型:厚膜电阻;阻值:1kΩ;精度:±1%;功率:100mW;工作电压:75V;温度系数:±100ppm/℃;; Manufacturer: UNI-ROYAL(厚声); AddInBom: yes; ModelId: fc143cca1e79419f9cd78b61e9279f080819f05c4eef4c71ace90d822a990e87; ModelTransform: 31.8897,63.7794,0,90,0,0,0,0,0; Tolerance: ±1%; Power(Watts): 100mW; Voltage-Supply(Max): 75V
R27 R28 = 0603WAF5101T5E: 电阻类型:厚膜电阻;阻值:5.1kΩ;精度:±1%;功率:100mW;工作电压:75V;温度系数:±100ppm/℃;; Manufacturer: UNI-ROYAL(厚声); AddInBom: yes; ModelId: fc143cca1e79419f9cd78b61e9279f080819f05c4eef4c71ace90d822a990e87; ModelTransform: 31.8897,63.7794,0,90,0,0,0,0,0; Tolerance: ±1%; Power(Watts): 100mW; Voltage-Supply(Max): 75V
R29-R31 = 0603WAF4701T5E: 电阻类型:厚膜电阻;阻值:4.7kΩ;精度:±1%;功率:100mW;工作电压:75V;温度系数:±100ppm/℃;; Manufacturer: UNI-ROYAL(厚声); AddInBom: yes; ModelId: fc143cca1e79419f9cd78b61e9279f080819f05c4eef4c71ace90d822a990e87; ModelTransform: 31.8897,63.7794,0,90,0,0,0,0,0; Tolerance: ±1%; Power(Watts): 100mW; Voltage-Supply(Max): 75V
SCREW1-SCREW3 = M3螺丝: Symbol: 螺丝孔; ConvertToPcb: yes
SW1 = SKRPACE010: 电路结构:单刀单掷;按钮形状:椭圆形按钮;安装方式:立贴;开关长度:4.2mm;开关宽度:3.2mm;开关高度:2.5mm;触点电流:50mA;额定电压:16V;带灯:-;工作寿命:-;; Manufacturer: ALPSALPINE(阿尔卑斯阿尔派); AddInBom: yes; ModelId: 38f4e5ae1c0a49d7a4c1f95a650cdbea0819f05c4eef4c71ace90d822a990e87; ModelName: KEY-SMD_4P-L4.2-W3.2-H2.5-LS4.6-P2.2; ModelTransform: 184.96971,125.984,0,0,0,0,0,-0.005,0; Circuit: 单刀单掷; Actuator Style: 椭圆形按钮; Switch Height: 2.5mm; Contact Current: 50mA; Voltage Rating: 16V
SW2 = SS-12D10L5: 电路结构:单刀双掷;安装方式:直插;开关颜色:黑色;额定电流(DC):3A;额定电压(DC):125V;额定电流(AC):3A;额定电压(AC):125V;机械寿命:1万次;; Manufacturer: XKB Connectivity(中国星坤); AddInBom: yes; ModelId: c49f07a32c154ec8ad7cf47670a53981; ModelName: SW-TH_L13.0-W6.8-H6.4-P4.7; ModelTransform: 511.81,267.716,0,0,0,0,0,0,-275.591; Circuit: 单刀双掷; Actuator Style: 矩形柱状; Pin Style: PC引脚; Switch Length: 13mm; Switch Width: 6.8mm; Switch Height: 6.4mm; Actuator Color: 黑色; Current Rating (DC): 3A; Voltage Rating (DC): 125V; Mechanical Life: 1万次
U1 = SN65HVD230DR: 类型:CAN收发器;数据速率:1Mbps;; Manufacturer: TI(德州仪器); AddInBom: yes; ModelId: e81d2f7d937b4a6ab1dca543ff5d56a40819f05c4eef4c71ace90d822a990e87; ModelName: SOIC-8_L4.9-W3.9-H1.7-LS6.0-P1.27; ModelTransform: 192.913,236.22,0,0,0,0,0,0,0; Data Rate: 1Mbps; Voltage - Supply: 3V~3.6V; Current - Supply: 17mA; Number of Channels: 1; Quiescent Supply Current: 370uA
U2 = STM32F407VET6: CPU内核:ARM Cortex-M4;CPU最大主频:168MHz;CPU位数:32 Bit;; Manufacturer: ST(意法半导体); Relevance: []; AddInBom: yes; ModelId: 469e6cc70557486dbd01fd12ff8149640819f05c4eef4c71ace90d822a990e87; ModelName: LQFP-100_L14.0-W14.0-H1.4-LS16.0-P0.50; ModelTransform: 629.92,629.92,0,0,0,0,0,0,0; CPU Maximum Speed: 168MHz; Core Size: 32 Bit; Program Storage Size: 512KB; Program Memory Type: FLASH; RAM Size: 192KB; Number of I/O: 82; ADC (Bit): 12bit; Oscillator Type: 内置; Voltage - Supply: 1.8V~3.6V
U3 = LMR14030SDDAR: 功能类型:降压型;工作电压:4V~40V;输出电压:800mV~28V;输出电流:3.5A;输出类型:可调;; Manufacturer: TI(德州仪器); AddInBom: yes; ModelId: 756fba4e187a48c69a2c935cd5c4465b0819f05c4eef4c71ace90d822a990e87; ModelName: SO-8_L4.9-W3.9-H1.5-LS5.9-P1.27; ModelTransform: 240.39054,192.913,0,270,0,0,0.004,-0.002,0; Function: 降压型; Voltage - Supply: 4V~40V; Output Current: 3.5A; Frequency - Switching: 2.5MHz; Synchronous Rectifier: 否; Number of Outputs: 1; Topology: 降压式; Quiescent Current: 40uA; Switch tube (built-in/external): 内置; Output Type: 可调
U4 = 0603WAF1003T5E: 电阻类型:厚膜电阻;阻值:100kΩ;精度:±1%;功率:100mW;最大工作电压:75V;温度系数:±100ppm/℃;; Manufacturer: UNI-ROYAL(厚声); 3D Model: fc143cca1e79419f9cd78b61e9279f08; 3D Model Transform: 31.8897,63.7794,0,90,0,0,0,0,0; Tolerance: ±1%; Power(Watts): 100mW; Overload Voltage (Max): 75V; AddInBom: yes
U5 = FH26W-21S-0.3SHW(60)_C3169719: 锁定特性:翻盖式;触点类型:下接;触点数量:21P;间距:0.3mm;安装方式:卧贴;工作温度:-55℃~+85℃;; Manufacturer: HRS(广濑); Add into BOM: yes; 3D Model: b5d9ec3d080745079c2273e10c5eaf9e; 3D Model Transform: 307.086,141.732,0,0,0,0,0,-11.811,0; Locking Feature: 翻盖式; Number of Contacts: 21P; Pitch: 0.3mm; FFC, FCB Thickness: 0.2mm
U6 = RT9013-33GB: 输出极性:正极;工作电压:5.5V;输出电压:3.3V;输出电流:500mA;电源纹波抑制比(PSRR):50dB@(10kHz);输出类型:固定;; Manufacturer: RICHTEK(立锜); AddInBom: yes; ModelId: 0a2a1b8f50944f73965918ad6e5fe1670819f05c4eef4c71ace90d822a990e87; ModelName: SOT-23-5_L2.9-W1.6-H1.1-LS2.8-P0.95; ModelTransform: 118.60433,114.173,0,90,0,0,0.0005,0.0005,0; Output Configuration: 正极; Voltage - Supply: 5.5V; Output Voltage: 3.3V; Output Current: 500mA; Voltage Dropout: 400mV@(500mA); standby current: 25uA; Noise: 30uVrms; Output Type: 固定; Number of Outputs: 1
U7 U9 = DRV8870DDAR: DRV8870 具有电流调节功能的 50V、3.6A、H 桥电机驱动器; Manufacturer: TI(德州仪器); AddInBom: yes; ModelId: aaf4e90098584f278f891a4d5ef3600d0819f05c4eef4c71ace90d822a990e87; ModelName: HSOP-8_L4.9-W3.9-H1.8-LS6.0-P1.27; ModelTransform: 248.031,192.913,0,90,0,0,0.0005,0.0005,0; Number of H-bridges: 1; Peak Current: 3.6A; RDS(on): 565mΩ; Quiescent Current(Iq): 10uA
U8 = SN65HVD230DR: 类型:CAN收发器;数据速率:1Mbps;; Manufacturer: TI(德州仪器); 3D Model: e81d2f7d937b4a6ab1dca543ff5d56a40819f05c4eef4c71ace90d822a990e87; 3D Model Transform: 192.913,236.22,0,0,0,0,0,0,0; Data Rate: 1Mbps; Voltage - Supply: 3V~3.6V; Current - Supply: 17mA; Number of Channels: 1; Quiescent Supply Current: 370uA; AddInBom: yes; ModelName: SOIC-8_L4.9-W3.9-H1.7-LS6.0-P1.27
U10 = DG305-5.0-02P-12-00A(H): 结构:1x2P;间距:5mm;颜色:蓝色;安装类型:直插;排数:1;每排PIN数:2;额定电流:20A;额定电压:250V;线规 - AWG:14~22;线规 - 平方毫米:1~2.5;工作温度:-30℃~+120℃;; Manufacturer: DEGSON(高正/高松); AddInBom: yes; ModelId: 88f12d9636094fcca081e76ba48821980819f05c4eef4c71ace90d822a990e87; ModelTransform: 417.322,354.33,0,0,0,0,-11.815,19.69,-196.85; Number of Positions or Pins: 1x2P; Pitch: 5mm; Number of PINs Per Row: 2; Screw Specification: M2.5; Current Rating: 20A; Voltage Rating (Max): 250V; Wire Gauge - AWG: 14~22; Wire Gauge - mm2: 1~2.5
U11 = MPU-6050: 传感器类型:IMU(加速度计+陀螺仪);接口类型:I2C;; Manufacturer: TDK InvenSense(应美盛); Symbol: MPU-6050_C24112; AddInBom: yes; ModelId: 3147e748bde04e038f0f2a42301e48160819f05c4eef4c71ace90d822a990e87; ModelTransform: 158.267,158.267,0,0,0,0,0,0,0; Accelerometer Sensing Axis: X,Y,Z; Acceleration Measurement Range (MAX): ±16g; Gyroscope Measurement Range (MAX): ±2000dps; Output Bits: 16bit; Interface: I2C; Voltage - Supply: 2.375V~3.46V; Cache Size: 1KB; Standby Current: 5uA
U12 U13 = WAFER-PH2.0-6PWB: 插针结构:1x6P;间距:2mm;安装方式:卧贴;参考系列:PH;总PIN数:6P;排数:1;每排PIN数:6;行距:-;额定电流:2A;触头材质:黄铜;触头镀层:锡;工作温度:-25℃~+85℃;; Manufacturer: XUNPU(讯普); AddInBom: yes; ModelId: 64a7c0100e2a4339a82dbd6d5b7dbb7d0819f05c4eef4c71ace90d822a990e87; ModelTransform: 629.92,334.645,0,0,0,0,0,-3.82,0; Pins Structure: 1x6P; Pitch: 2mm; Reference Series: PH; Number of PINs Per Row: 6; Current Rating: 2A; Voltage Rating: 250V; Plastic Material: LCP; Supplementary Features: 辅助焊脚; Z-Height of the Board: 5.6mm; X-Length of Bottom Edge on Board (Spacing Line): 16mm; Y-Width of Bottom Edge on Board: 7.59mm
U14 = CH340N: 应用功能:USB转串口;USB协议版本:USB 2.0;通道数:1;数据速率:2Mbps;; Manufacturer: WCH(南京沁恒); Symbol: CH340N_C2977777; AddInBom: yes; ModelId: 75c24a7891ee4dd6bdac16a7163ff87e0819f05c4eef4c71ace90d822a990e87; ModelName: SOP-8_L4.9-W3.9-P1.27-LS6.0-BL-1; ModelTransform: 192.913,236.22,0,0,0,0,-0.393,2.749,0; Applications Function: USB转串口; USB Protocol: USB 2.0; Number of Channels: 1; Voltage - Supply: 3.3V；5V; Data Rate: 2Mbps
U15 = RT0603BRD0717K8L: 电阻类型:薄膜电阻;阻值:17.8kΩ;精度:±0.1%;功率:100mW;最大工作电压:75V;温度系数:±25ppm/℃;; Manufacturer: YAGEO(国巨); 3D Model: fc143cca1e79419f9cd78b61e9279f08; 3D Model Transform: 31.8897,63.7794,0,90,0,0,0,0,0; Tolerance: ±0.1%; Power(Watts): 100mW; Overload Voltage (Max): 75V; AddInBom: yes
USB1 = TYPE-C 16PIN 2MD(073): 连接器类型:Type-C;协议标准:-;公母:母;安装方式:卧贴;触点数量:16P;端口数量:1;额定电流 - 电源:3A;工作温度:-25℃~+85℃;; Manufacturer: SHOU HAN(首韩); AddInBom: yes; ModelId: 3a41b9ec9b654a0fad4d118405ec62900819f05c4eef4c71ace90d822a990e87; ModelName: USB-C-SMD_TYPE-C-6PIN-2MD-073; ModelTransform: 351.9678,298.4246,0,0,0,0,0,-47.244,-35.433; Gender: 母; Number of Contacts: 16P; Number of Ports: 1; Current Rating-Power: 3A; Voltage Rating: 5V; Connect-Disconnect Life: 1万次; Detection color: 黑色
X1 = X32258MSB4SI: 晶振类型:贴片晶振;频率:8MHz;常温频差:±10ppm;负载电容:20pF;频率稳定度:±20ppm;; Manufacturer: YXC(扬兴晶振); AddInBom: yes; ModelId: ff2dfd5650294453a14147960efe18380819f05c4eef4c71ace90d822a990e87; ModelTransform: 125.984,98.425,0,0,0,0,0,0,0; Normal temperature Frequency Tolerance: ±10ppm; Load Capacitance: 20pF; Frequency Stability: ±20ppm; Equivalent Series Resistance(ESR): 180Ω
